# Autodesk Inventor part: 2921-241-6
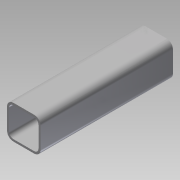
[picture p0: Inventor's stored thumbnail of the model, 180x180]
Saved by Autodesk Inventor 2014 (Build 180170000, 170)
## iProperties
Company: NHTSA/VRTC
Created: 2011-11
Part Number: 2921-241-6
Material: Steel
Document SubType Name: Modeling
Designer: Dave Walker
Density: 7.85 g/cm^3
Description: T.S. 2" x 2" x 1/8" x 200.2mm (7.88")
Mass: 881.46 g
Surface Area: 718.543 cm^2
Volume: 112.288 cm^3
Project: CHILD SIDE IMACT SLED
Stock Number: IMPACTOR FRAME TUBE 6
Appearance: Steel
Author: Dave Walker
Title: Impactor Frame Tube 6
Subject: Child Side Impact Sled
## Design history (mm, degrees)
node "Sketch1"
node "2921-105-61"
sketch "Sketch2"
  geometry: L1 (31.496, 50.8)-(0, 50.8) reference; L2 (-9.652, 41.148)-(-9.652, 9.652) reference; L3 (0, 0)-(31.496, 0) reference; L4 (41.148, 9.652)-(41.148, 41.148) reference; L5 (31.496, 47.625)-(0, 47.625) reference; L6 (-6.477, 41.148)-(-6.477, 9.652) reference; L7 (0, 3.175)-(31.496, 3.175) reference; L8 (37.973, 9.652)-(37.973, 41.148) reference; A1 r 9.652 centre (0, 41.148) between (0, 50.8) and (-9.652, 41.148) reference; A2 r 9.652 centre (0, 9.652) between (-9.652, 9.652) and (0, 0) reference; A3 r 9.652 centre (31.496, 9.652) between (31.496, 0) and (41.148, 9.652) reference; A4 r 9.652 centre (31.496, 41.148) between (41.148, 41.148) and (31.496, 50.8) reference; A5 r 6.477 centre (0, 41.148) between (0, 47.625) and (-6.477, 41.148) reference; A6 r 6.477 centre (0, 9.652) between (-6.477, 9.652) and (0, 3.175) reference; A7 r 6.477 centre (31.496, 9.652) between (31.496, 3.175) and (37.973, 9.652) reference; A8 r 6.477 centre (31.496, 41.148) between (37.973, 41.148) and (31.496, 47.625) reference; 1 further point
extrude "Extrusion1" join sketch "Sketch2" distance "d0" = 0.175; taper "d1" = 0 deg
node "2921-105-6"
node "Base1"
